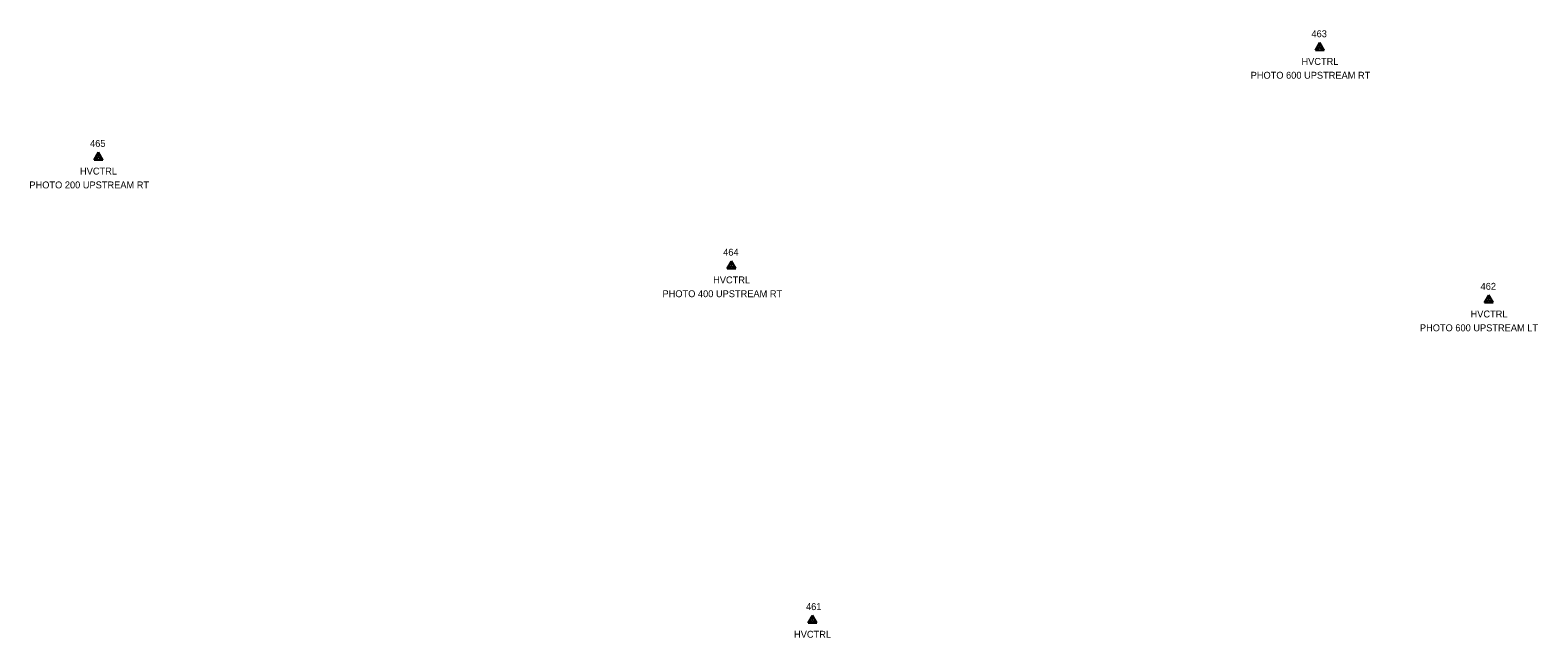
# Model space of a CAD drawing. Extents: x 89316 to 92454, y 84175 to 86051.
# Drawn here: x 92017.7 to 92453.9, y 84190.1 to 84365.8 of the extents above; entities that cross this region are included whole.
import ezdxf

# ---------------------------------------------------------------- set-up
doc = ezdxf.new("R2010")
doc.units = 0
for name, color, linetype in [('C_A', 7, 'Continuous'), ('C_C', 7, 'Continuous'), ('C_I', 7, 'Continuous'), ('CPSM', 7, 'Continuous')]:
    doc.layers.add(name, color=color, linetype=linetype)

msp = doc.modelspace()

# ---------------------------------------------------------------- linework, layer by layer
at = {"layer": 'CPSM'}
for p, q in [((92389.53, 84360.03), (92390.78, 84362.2)), ((92392.03, 84360.03), (92390.78, 84362.2)), ((92390.78, 84360.75), (92390.78, 84362.2)), ((92389.53, 84360.03), (92390.78, 84360.75)), ((92389.53, 84360.03), (92392.03, 84360.03)), ((92390.78, 84360.75), (92390.78, 84360.75)), ((92390.78, 84360.75), (92392.03, 84360.03)), ((92036.17, 84328.3), (92037.42, 84330.47)), ((92036.17, 84328.3), (92037.42, 84329.03)), ((92036.17, 84328.3), (92038.67, 84328.3)), ((92038.67, 84328.3), (92037.42, 84330.47)), ((92037.42, 84329.03), (92037.42, 84330.47)), ((92037.42, 84329.03), (92037.42, 84329.03)), ((92037.42, 84329.03), (92038.67, 84328.3)), ((92219.33, 84296.85), (92220.58, 84299.02)), ((92219.33, 84296.85), (92220.58, 84297.57)), ((92219.33, 84296.85), (92221.83, 84296.85)), ((92221.83, 84296.85), (92220.58, 84299.02)), ((92220.58, 84297.57), (92220.58, 84299.02)), ((92220.58, 84297.57), (92220.58, 84297.57)), ((92220.58, 84297.57), (92221.83, 84296.85)), ((92438.45, 84286.99), (92439.7, 84289.15)), ((92438.45, 84286.99), (92439.7, 84287.71)), ((92440.95, 84286.99), (92439.7, 84289.15)), ((92439.7, 84287.71), (92439.7, 84289.15)), ((92439.7, 84287.71), (92439.7, 84287.71)), ((92439.7, 84287.71), (92440.95, 84286.99)), ((92438.45, 84286.99), (92440.95, 84286.99)), ((92242.73, 84194.37), (92243.98, 84196.53)), ((92245.23, 84194.37), (92243.98, 84196.53)), ((92243.98, 84195.09), (92243.98, 84196.53)), ((92242.73, 84194.37), (92243.98, 84195.09)), ((92242.73, 84194.37), (92245.23, 84194.37)), ((92243.98, 84195.09), (92243.98, 84195.09)), ((92243.98, 84195.09), (92245.23, 84194.37))]:
    msp.add_line(p, q, dxfattribs=at)

# ---------------------------------------------------------------- texts
at = {"layer": 'C_A'}
for p in [(92385.47, 84355.75), (92032.11, 84324.03), (92215.27, 84292.57), (92434.39, 84282.71), (92238.68, 84190.09)]:
    msp.add_text('HVCTRL', height=2, dxfattribs=at).set_placement(p)
at = {"layer": 'C_C'}
for s, p in [('PHOTO 600 UPSTREAM RT', (92370.77, 84351.75)), ('PHOTO 200 UPSTREAM RT', (92017.46, 84320.03)), ('PHOTO 400 UPSTREAM RT', (92200.62, 84288.57)), ('PHOTO 600 UPSTREAM LT', (92419.74, 84278.71))]:
    msp.add_text(s, height=2, dxfattribs=at).set_placement(p)
at = {"layer": 'C_I'}
for s, p in [('463', (92388.37, 84363.75)), ('465', (92035.01, 84332.03)), ('464', (92218.17, 84300.57)), ('462', (92437.29, 84290.71)), ('461', (92242.14, 84198.09))]:
    msp.add_text(s, height=2, dxfattribs=at).set_placement(p)

doc.saveas('drawing.dxf')
